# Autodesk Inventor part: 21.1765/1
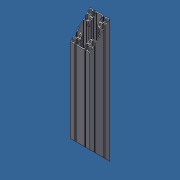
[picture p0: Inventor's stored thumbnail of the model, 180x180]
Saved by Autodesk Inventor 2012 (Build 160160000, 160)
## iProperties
Created: 2007-07
Part Number: 21.1765/1
Material: Aluminum-6061
Document SubType Name: Modeling
Designer: Andy Moles
Density: 2.71 g/cm^3
Description: L = 22", MILL TO 21.1765/1
Stock Number: 20.1010 PROFILE 90X90 L
Vendor: F
Mass: 2512.28 g
Surface Area: 5761.57 cm^2
Volume: 927.042 cm^3
Author: Andy Moles
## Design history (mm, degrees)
sketch "Sketch1"
  geometry: L1 (26.6, 45)-(26.6, 40.5) reference; L2 (26.6, 40.5)-(29.3, 40.5) reference; L3 (29.3, 40.5)-(29.3, 32) reference; L4 (29.3, 32)-(27, 29.7) reference; L5 (27, 29.7)-(18, 29.7) reference; L6 (18, 29.7)-(15.7, 32) reference; L7 (15.7, 32)-(15.7, 40.5) reference; L8 (15.7, 40.5)-(18.4, 40.5) reference; L9 (18.4, 40.5)-(18.4, 45) reference; L10 (-18.4, 45)-(18.4, 45) reference; L11 (-18.4, 45)-(-18.4, 40.5) reference; L12 (-18.4, 40.5)-(-15.7, 40.5) reference; L13 (-15.7, 40.5)-(-15.7, 32) reference; L14 (-15.7, 32)-(-18, 29.7) reference; L15 (-18, 29.7)-(-27, 29.7) reference; L16 (-27, 29.7)-(-29.3, 32) reference; L17 (-29.3, 32)-(-29.3, 40.5) reference; L18 (-29.3, 40.5)-(-26.6, 40.5) reference; L19 (-26.6, 40.5)-(-26.6, 45) reference; L20 (-45, 45)-(-26.6, 45) reference; L21 (-45, 26.6)-(-45, 45) reference; L22 (-45, 26.6)-(-40.5, 26.6) reference; L23 (-40.5, 26.6)-(-40.5, 29.3) reference; L24 (-40.5, 29.3)-(-32, 29.3) reference; L25 (-32, 29.3)-(-29.7, 27) reference; L26 (-29.7, 27)-(-29.7, 18) reference; L27 (-29.7, 18)-(-32, 15.7) reference; L28 (-32, 15.7)-(-40.5, 15.7) reference; L29 (-40.5, 15.7)-(-40.5, 18.4) reference; L30 (-40.5, 18.4)-(-45, 18.4) reference; L31 (-45, -18.4)-(-45, 18.4) reference; L32 (-45, -18.4)-(-40.5, -18.4) reference; L33 (-40.5, -18.4)-(-40.5, -15.7) reference; L34 (-40.5, -15.7)-(-32, -15.7) reference; L35 (-32, -15.7)-(-29.7, -18) reference; L36 (-29.7, -18)-(-29.7, -27) reference; L37 (-29.7, -27)-(-32, -29.3) reference; L38 (-32, -29.3)-(-40.5, -29.3) reference; L39 (-40.5, -29.3)-(-40.5, -26.6) reference; L40 (-40.5, -26.6)-(-45, -26.6) reference; L41 (-45, -45)-(-45, -26.6) reference; L42 (-26.6, -45)-(-45, -45) reference; L43 (-26.6, -45)-(-26.6, -40.5) reference; L44 (-26.6, -40.5)-(-29.3, -40.5) reference; L45 (-29.3, -40.5)-(-29.3, -32) reference; L46 (-29.3, -32)-(-27, -29.7) reference; L47 (-27, -29.7)-(-18, -29.7) reference; L48 (-18, -29.7)-(-15.7, -32) reference; L49 (-15.7, -32)-(-15.7, -40.5) reference; L50 (-15.7, -40.5)-(-18.4, -40.5) reference; L51 (-18.4, -40.5)-(-18.4, -45) reference; L52 (18.4, -45)-(-18.4, -45) reference; L53 (18.4, -45)-(18.4, -40.5) reference; L54 (18.4, -40.5)-(15.7, -40.5) reference; L55 (15.7, -40.5)-(15.7, -32) reference; L56 (15.7, -32)-(18, -29.7) reference; L57 (18, -29.7)-(27, -29.7) reference; L58 (27, -29.7)-(29.3, -32) reference; L59 (29.3, -32)-(29.3, -40.5) reference; L60 (29.3, -40.5)-(26.6, -40.5) reference; L61 (26.6, -40.5)-(26.6, -45) reference; L62 (45, -45)-(26.6, -45) reference; L63 (45, -26.6)-(45, -45) reference; L64 (45, -26.6)-(40.5, -26.6) reference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; C1 r 3.75 at (22.5, 22.5) reference; C2 r 3.75 at (-22.5, 22.5) reference; C3 r 3.75 at (22.5, -22.5) reference; C4 r 3.75 at (-22.5, -22.5) reference; C5 r 5.85 at (37.15, 37.15) reference; C6 r 5.85 at (-37.15, 37.15) reference; C7 r 5.85 at (37.15, -37.15) reference; C8 r 5.85 at (-37.15, -37.15) reference; A1 r 1 centre (-41, -12.7) between (-42, -12.7) and (-41, -13.7) reference; A2 r 1 centre (-41, 12.7) between (-41, 13.7) and (-42, 12.7) reference; A3 r 2 centre (-29.241, 15.7) between (-29.241, 13.7) and (-28.765, 13.757) reference; A4 r 7 centre (-22.5, 22.5) between (-20.834, 15.701) and (-15.701, 20.834) reference; A5 r 2 centre (-15.7, 29.241) between (-13.757, 28.765) and (-13.7, 29.241) reference; A6 r 1 centre (-12.7, 41) between (-12.7, 42) and (-13.7, 41) reference; A7 r 1 centre (12.7, 41) between (13.7, 41) and (12.7, 42) reference; A8 r 2 centre (15.7, 29.241) between (13.7, 29.241) and (13.757, 28.765) reference; A9 r 7 centre (22.5, 22.5) between (15.701, 20.834) and (20.834, 15.701) reference; A10 r 2 centre (29.241, 15.7) between (28.765, 13.757) and (29.241, 13.7) reference; A11 r 1 centre (41, 12.7) between (42, 12.7) and (41, 13.7) reference; A12 r 1 centre (41, -12.7) between (41, -13.7) and (42, -12.7) reference; A13 r 2 centre (29.241, -15.7) between (29.241, -13.7) and (28.765, -13.757) reference; A14 r 7 centre (22.5, -22.5) between (20.834, -15.701) and (15.701, -20.834) reference; A15 r 2 centre (15.7, -29.241) between (13.757, -28.765) and (13.7, -29.241) reference; A16 r 1 centre (12.7, -41) between (12.7, -42) and (13.7, -41) reference; A17 r 1 centre (-12.7, -41) between (-13.7, -41) and (-12.7, -42) reference; A18 r 2 centre (-15.7, -29.241) between (-13.7, -29.241) and (-13.757, -28.765) reference; A19 r 7 centre (-22.5, -22.5) between (-15.701, -20.834) and (-20.834, -15.701) reference; A20 r 2 centre (-29.241, -15.7) between (-28.765, -13.757) and (-29.241, -13.7) reference
  constraints: 208 end point, 42 parallel, 41 horizontal, 41 vertical, 40 point on circle, 40 tangent, 28 centre point, 22 equal radius, 4 coincident with centre, 3 perpendicular, 204 other
extrude "Extrusion1" new body sketch "Sketch1" stored distance "d175" = 558.8 (= LENGTH); taper "d176" = 0 deg
sketch "Sketch2"
  geometry: L1 (0, 63.4)-(0, 45) reference; L2 (558.8, 63.4)-(0, 63.4) reference; L3 (558.8, -26.6)-(0, -26.6) reference; L4 (558.8, 45)-(558.8, 63.4) reference; L5 (0, 63.4)-(90, -26.6); L6 (90, -26.6)-(0, -26.6); L7 (0, -26.6)-(0, 63.4); 1 further point
  constraints: 6 end point, 2 collinear, 1 point on line
  dimensions: "d177" = 45 deg angle of L5 L7
extrude "Extrusion2" cut sketch "Sketch2" stored distance "d178" = 558.8; taper "d179" = 0 deg
workplane "Work Plane1"
sketch "Sketch3"
  geometry: L1 (0, 127.279)-(36.8, 127.279) reference; L2 (63.4, -267.852)-(63.4, 127.279) reference; C1 r 6.5 at (40.9, 75.209); C2 r 6.5 at (40.9, 11.455); C3 r 6.5 at (-4.1, 11.455); C4 r 6.5 at (-4.1, 75.209); 1 further point
  constraints: 4 centre point, 2 horizontal alignment, 2 vertical alignment
  dimensions: "d181" = 13 diameter of C2; "d182" = 13 diameter of C1; "d183" = 13 diameter of C4; "d184" = 13 diameter of C3; "d185" = 22.5 distance from line of C1.centre L2; "d186" = 67.5 distance from line of C4.centre L2; "d187" = 52.07 distance from line of C4.centre L1; "d188" = 115.824 distance from line of C3.centre L1
extrude "Extrusion3" cut sketch "Sketch3" stored distance "d189" = 558.8; taper "d190" = 0 deg
sketch "Sketch4"
  geometry: A1 r 6.5 centre (40.9, 75.209) between (45, 70.165) and (45, 80.253) reference; A2 r 6.5 centre (-4.1, 75.209) between (0, 70.165) and (0, 80.253) reference; A3 r 6.5 centre (-4.1, 11.455) between (0, 6.411) and (0, 16.499) reference; A4 r 6.5 centre (40.9, 11.455) between (45, 6.411) and (45, 16.499) reference; 5 further points
  constraints: 4 coincident
hole "Hole1" sketch "Sketch4" at (40.9, 75.209), (40.9, 11.455), (-4.1, 11.455), (-4.1, 75.209) diameter "d191" = 8.5; stored, may be unused: countersink angle "d195" = 82 deg, drill point angle "d197" = 118 deg; dims "d192" = 12.7, "d193" = 9.525, "d194" = 6.35, "d196" = 19.05
mirror "Mirror1"
body "Solid1"
workplane "Work Plane2"
other parameters: "LENGTH" = 558.8 [user parameter; used in 1 equation term], "d180" = -21.59
